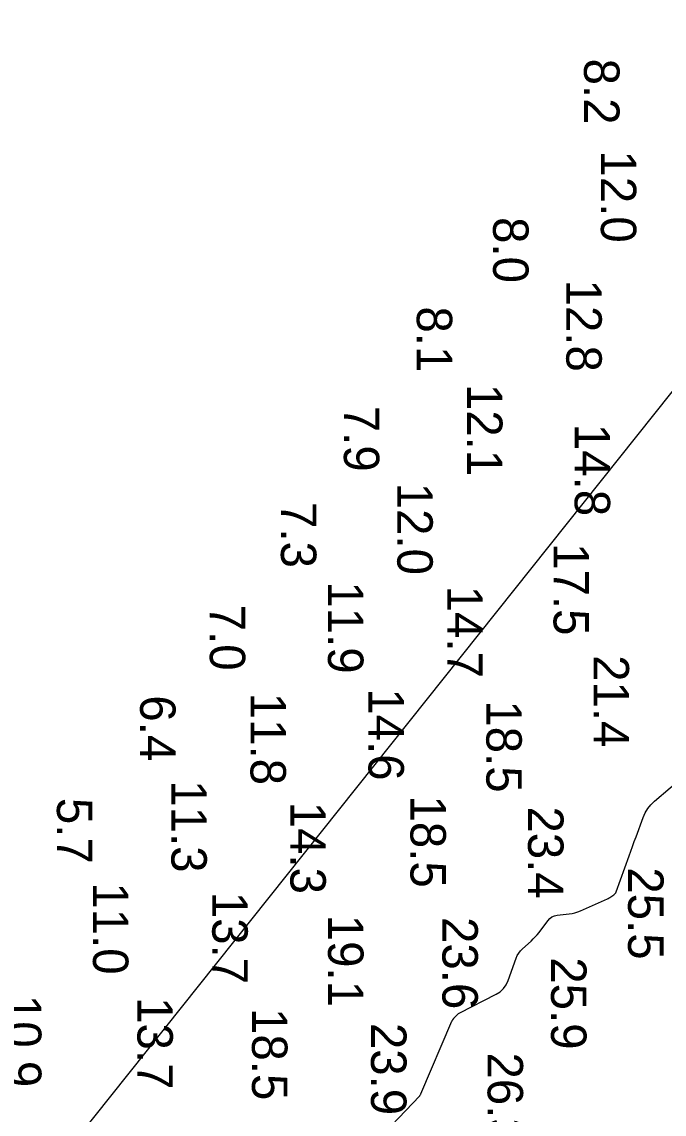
# Model space of a CAD drawing. Extents: x 1178573 to 1187098, y 693282 to 751751.
# Drawn here: x 1185820.2 to 1186046.8, y 726824.7 to 727209.8 of the extents above; entities that cross this region are included whole.
import ezdxf

# ---------------------------------------------------------------- set-up
doc = ezdxf.new("R2010")
doc.units = 0
for name, color, linetype in [('G-ANNO-PATT', 7, 'Continuous'), ('V-HYDS-MAJR', 7, 'Continuous'), ('V-HYDS-SOUN', 7, 'Continuous')]:
    doc.layers.add(name, color=color, linetype=linetype)

msp = doc.modelspace()

# ---------------------------------------------------------------- linework, layer by layer
at = {"layer": 'G-ANNO-PATT'}
for p, q in [((1186159.57, 727217.45), (1185663.01, 726594.83)), ((1186043.43, 726935.08), (1186054.42, 726944.51)), ((1186040.14, 726930.96), (1186041.05, 726932.46)), ((1186041.05, 726932.46), (1186042.15, 726933.83)), ((1186042.15, 726933.83), (1186043.43, 726935.08)), ((1186036.88, 726922.55), (1186039.41, 726929.33)), ((1186039.41, 726929.33), (1186040.14, 726930.96)), ((1186035.63, 726919.15), (1186036.25, 726920.85)), ((1186036.25, 726920.85), (1186036.88, 726922.55)), ((1186034.39, 726915.75), (1186035.01, 726917.45)), ((1186035.01, 726917.45), (1186035.63, 726919.15)), ((1186029.86, 726903.12), (1186034.39, 726915.75)), ((1186027.08, 726900.8), (1186027.38, 726900.96)), ((1186027.38, 726900.96), (1186027.67, 726901.13)), ((1186027.67, 726901.13), (1186027.95, 726901.32)), ((1186027.95, 726901.32), (1186029.07, 726902.09)), ((1186029.07, 726902.09), (1186029.33, 726902.3)), ((1186029.33, 726902.3), (1186029.54, 726902.55)), ((1186029.54, 726902.55), (1186029.72, 726902.82)), ((1186029.72, 726902.82), (1186029.86, 726903.12)), ((1186017.26, 726896.42), (1186026.77, 726900.65)), ((1186026.77, 726900.65), (1186027.08, 726900.8)), ((1186005.72, 726892.93), (1186006.4, 726893.68)), ((1186006.4, 726893.68), (1186007.19, 726894.25)), ((1186007.19, 726894.25), (1186008.08, 726894.64)), ((1186008.08, 726894.64), (1186009.07, 726894.85)), ((1186009.07, 726894.85), (1186013.25, 726895.32)), ((1186013.25, 726895.32), (1186014.29, 726895.48)), ((1186014.29, 726895.48), (1186015.3, 726895.72)), ((1186015.3, 726895.72), (1186016.29, 726896.03)), ((1186016.29, 726896.03), (1186017.26, 726896.42)), ((1186002.64, 726888.82), (1186005.72, 726892.93)), ((1185996.8, 726883.01), (1185999.87, 726885.78)), ((1185999.87, 726885.78), (1186000.62, 726886.49)), ((1186000.62, 726886.49), (1186001.33, 726887.23)), ((1186001.33, 726887.23), (1186002.01, 726888.01)), ((1186002.01, 726888.01), (1186002.64, 726888.82)), ((1185995.47, 726881.48), (1185996.08, 726882.28)), ((1185996.08, 726882.28), (1185996.8, 726883.01)), ((1185991.76, 726871.83), (1185994.57, 726879.68)), ((1185994.57, 726879.68), (1185994.97, 726880.62)), ((1185994.97, 726880.62), (1185995.47, 726881.48)), ((1185990.11, 726868.99), (1185991.06, 726870.3)), ((1185991.06, 726870.3), (1185991.76, 726871.83)), ((1185974.67, 726860.46), (1185987.51, 726866.99)), ((1185987.51, 726866.99), (1185988.93, 726867.88)), ((1185988.93, 726867.88), (1185990.11, 726868.99)), ((1185972.54, 726858.5), (1185972.63, 726858.62)), ((1185972.63, 726858.62), (1185972.72, 726858.73)), ((1185972.72, 726858.73), (1185972.82, 726858.84)), ((1185972.82, 726858.84), (1185972.92, 726858.95)), ((1185972.92, 726858.95), (1185973.83, 726859.85)), ((1185973.83, 726859.85), (1185974.03, 726860.02)), ((1185974.03, 726860.02), (1185974.23, 726860.18)), ((1185974.23, 726860.18), (1185974.45, 726860.33)), ((1185974.45, 726860.33), (1185974.67, 726860.46)), ((1185960.96, 726831.85), (1185971.9, 726857.49)), ((1185971.9, 726857.49), (1185971.96, 726857.63)), ((1185971.96, 726857.63), (1185972.03, 726857.76)), ((1185972.03, 726857.76), (1185972.11, 726857.89)), ((1185972.11, 726857.89), (1185972.19, 726858.01)), ((1185972.19, 726858.01), (1185972.54, 726858.5)), ((1185960.74, 726831.43), (1185960.85, 726831.64)), ((1185960.85, 726831.64), (1185960.88, 726831.69)), ((1185960.88, 726831.69), (1185960.91, 726831.74)), ((1185960.91, 726831.74), (1185960.94, 726831.8)), ((1185960.94, 726831.8), (1185960.96, 726831.85)), ((1185948.16, 726818.12), (1185960.6, 726831.24)), ((1185960.6, 726831.24), (1185960.64, 726831.28)), ((1185960.64, 726831.28), (1185960.67, 726831.33)), ((1185960.67, 726831.33), (1185960.71, 726831.38)), ((1185960.71, 726831.38), (1185960.74, 726831.43))]:
    msp.add_line(p, q, dxfattribs=at)
at = {"layer": 'V-HYDS-MAJR'}
msp.add_lwpolyline([(1185948.16, 726818.12), (1185960.6, 726831.24), (1185960.64, 726831.28), (1185960.67, 726831.33), (1185960.71, 726831.38), (1185960.74, 726831.43), (1185960.85, 726831.64), (1185960.88, 726831.69), (1185960.91, 726831.74), (1185960.94, 726831.8), (1185960.96, 726831.85), (1185971.9, 726857.49), (1185971.96, 726857.63), (1185972.03, 726857.76), (1185972.11, 726857.89), (1185972.19, 726858.01), (1185972.54, 726858.5), (1185972.63, 726858.62), (1185972.72, 726858.73), (1185972.82, 726858.84), (1185972.92, 726858.95), (1185973.83, 726859.85), (1185974.03, 726860.02), (1185974.23, 726860.18), (1185974.45, 726860.33), (1185974.67, 726860.46), (1185987.51, 726866.99), (1185988.93, 726867.88), (1185990.11, 726868.99), (1185991.06, 726870.3), (1185991.76, 726871.83), (1185994.57, 726879.68), (1185994.97, 726880.62), (1185995.47, 726881.48), (1185996.08, 726882.28), (1185996.8, 726883.01), (1185999.87, 726885.78), (1186000.62, 726886.49), (1186001.33, 726887.23), (1186002.01, 726888.01), (1186002.64, 726888.82), (1186005.72, 726892.93), (1186006.4, 726893.68), (1186007.19, 726894.25), (1186008.08, 726894.64), (1186009.07, 726894.85), (1186013.25, 726895.32), (1186014.29, 726895.48), (1186015.3, 726895.72), (1186016.29, 726896.03), (1186017.26, 726896.42), (1186026.77, 726900.65), (1186027.08, 726900.8), (1186027.38, 726900.96), (1186027.67, 726901.13), (1186027.95, 726901.32), (1186029.07, 726902.09), (1186029.33, 726902.3), (1186029.54, 726902.55), (1186029.72, 726902.82), (1186029.86, 726903.12), (1186034.39, 726915.75), (1186035.01, 726917.45), (1186035.63, 726919.15), (1186036.25, 726920.85), (1186036.88, 726922.55), (1186039.41, 726929.33), (1186040.14, 726930.96), (1186041.05, 726932.46), (1186042.15, 726933.83), (1186043.43, 726935.08), (1186054.42, 726944.51)], dxfattribs=at)

# ---------------------------------------------------------------- texts
at = {"layer": 'V-HYDS-SOUN'}
for s, p in [('8.2', (1186018.53, 727196.85)), ('12.0 ', (1186024.46, 727164.48)), ('8.0', (1185986.44, 727140.99)), ('12.8 ', (1186012.27, 727118.96)), ('8.1', (1185959.51, 727109.49)), ('12.1 ', (1185977.23, 727082.18)), ('7.9', (1185933.79, 727074.46)), ('14.8 ', (1186015.22, 727068.08)), ('12.0 ', (1185952.64, 727047.35)), ('7.3', (1185911.58, 727040.53)), ('17.5 ', (1186007.77, 727026.03)), ('11.9 ', (1185928.18, 727012.57)), ('14.7 ', (1185970.26, 727011.06)), ('7.0', (1185886.48, 727004.34)), ('21.4 ', (1186021.9, 726986.56)), ('6.4', (1185861.9, 726972.39)), ('11.8 ', (1185900.85, 726973.29)), ('14.6 ', (1185942.47, 726974.87)), ('18.5 ', (1185984.05, 726970.62)), ('11.3 ', (1185872.92, 726942.45)), ('5.7', (1185832.54, 726936.23)), ('18.5 ', (1185957.28, 726937.09)), ('14.3 ', (1185914.91, 726934.88)), ('23.4 ', (1185998.77, 726933.21)), ('25.5 ', (1186034.08, 726911.76)), ('11.0 ', (1185845.26, 726906.47)), ('13.7 ', (1185887.35, 726903.12)), ('19.1 ', (1185928.21, 726895.04)), ('23.6 ', (1185968.55, 726894.23)), ('25.9 ', (1186006.89, 726880.05)), ('10.9 ', (1185814.56, 726866.77)), ('13.7 ', (1185860.94, 726865.98)), ('18.5 ', (1185901.37, 726862.15)), ('23.9 ', (1185943.37, 726856.92)), ('26.3 ', (1185984.5, 726846.49))]:
    msp.add_text(s, height=12.5, rotation=270, dxfattribs=at).set_placement(p)

doc.saveas('drawing.dxf')
